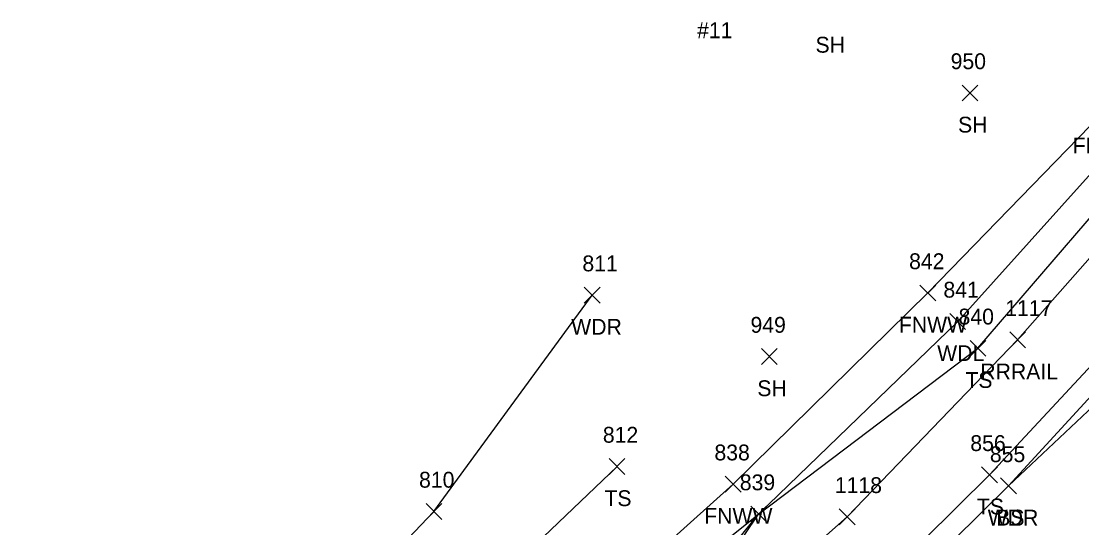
# Model space of a CAD drawing. Extents: x 1764889 to 1767296, y 695936 to 698960.
# Drawn here: x 1766131.8 to 1766265.6, y 696453.4 to 696517.3 of the extents above; entities that cross this region are included whole.
import ezdxf

# ---------------------------------------------------------------- set-up
doc = ezdxf.new("R2010")
doc.units = 0
for name, color, linetype in [('L_A', 7, 'Continuous'), ('L_I', 7, 'Continuous'), ('L_TIC', 7, 'Continuous'), ('LAWA', 7, 'Continuous'), ('LELB', 7, 'Continuous'), ('LFNC', 7, 'Continuous'), ('R_A', 7, 'Continuous'), ('R_I', 7, 'Continuous'), ('R_TIC', 7, 'Continuous'), ('RR', 7, 'Continuous'), ('U_C', 7, 'Continuous')]:
    doc.layers.add(name, color=color, linetype=linetype)

msp = doc.modelspace()

# ---------------------------------------------------------------- linework, layer by layer
at = {"layer": 'L_TIC'}
for points in [[(1766250.52, 696507.28), (1766252.52, 696509.28)], [(1766252.52, 696507.28), (1766250.52, 696509.28)], [(1766202.84, 696481.78), (1766204.84, 696483.78)], [(1766204.84, 696481.78), (1766202.84, 696483.78)], [(1766245.19, 696482.05), (1766247.19, 696484.05)], [(1766247.19, 696482.05), (1766245.19, 696484.05)], [(1766248.96, 696478.46), (1766250.96, 696480.46)], [(1766250.96, 696478.46), (1766248.96, 696480.46)], [(1766251.52, 696475.07), (1766253.52, 696477.07)], [(1766253.52, 696475.07), (1766251.52, 696477.07)], [(1766225.19, 696474.03), (1766227.19, 696476.03)], [(1766227.19, 696474.03), (1766225.19, 696476.03)], [(1766205.98, 696460.16), (1766207.98, 696462.16)], [(1766207.98, 696460.16), (1766205.98, 696462.16)], [(1766252.97, 696459.11), (1766254.97, 696461.11)], [(1766254.97, 696459.11), (1766252.97, 696461.11)], [(1766220.63, 696457.93), (1766222.63, 696459.93)], [(1766222.63, 696457.93), (1766220.63, 696459.93)], [(1766255.38, 696457.71), (1766257.38, 696459.71)], [(1766257.38, 696457.71), (1766255.38, 696459.71)], [(1766255.38, 696457.71), (1766257.38, 696459.71)], [(1766257.38, 696457.71), (1766255.38, 696459.71)], [(1766182.88, 696454.49), (1766184.88, 696456.49)], [(1766184.88, 696454.49), (1766182.88, 696456.49)], [(1766223.84, 696454.16), (1766225.84, 696456.16)], [(1766225.84, 696454.16), (1766223.84, 696456.16)], [(1766223.84, 696454.16), (1766225.84, 696456.16)], [(1766225.84, 696454.16), (1766223.84, 696456.16)], [(1766223.84, 696454.16), (1766225.84, 696456.16)], [(1766225.84, 696454.16), (1766223.84, 696456.16)]]:
    msp.add_lwpolyline(points, dxfattribs=at)
at = {"layer": 'LAWA'}
for points in [[(1766155.54, 696397.9), (1766161.77, 696405.44), (1766181.88, 696420.14), (1766196.06, 696430.7), (1766216.12, 696448.15), (1766224.84, 696455.16), (1766249.96, 696479.46), (1766272.12, 696504.03), (1766288.24, 696524.91), (1766311.88, 696556.72), (1766301.19, 696567.63)], [(1766161.11, 696377.48), (1766185.12, 696394.62), (1766212.55, 696417.35), (1766235.34, 696437.94), (1766256.38, 696458.71), (1766279.26, 696480.23), (1766298.66, 696503.53), (1766311.89, 696514.91), (1766320.79, 696513.88), (1766319.44, 696504.93), (1766321.82, 696491.21)], [(1766142.08, 696412.96), (1766162.91, 696433.47), (1766183.88, 696455.49), (1766203.84, 696482.78)]]:
    msp.add_lwpolyline(points, dxfattribs=at)
at = {"layer": 'LELB'}
for points in [[(1766158.91, 696379.33), (1766183.1, 696397.73), (1766210.95, 696420.2), (1766233.27, 696439.62), (1766253.97, 696460.11), (1766276.48, 696484.28), (1766294.63, 696506.78), (1766322.62, 696540.3)], [(1766256.38, 696458.71), (1766277.79, 696482.01), (1766297.06, 696504.51), (1766322.62, 696540.3)], [(1766150.56, 696387.79), (1766167.12, 696399.48), (1766186.95, 696417.34), (1766197.67, 696430.72), (1766217.09, 696445.57), (1766224.84, 696455.16), (1766252.52, 696476.07), (1766275.69, 696502.98), (1766288.24, 696524.91)], [(1766150.99, 696407.72), (1766172.83, 696427.73), (1766192.16, 696447.01), (1766206.98, 696461.16)], [(1766200.91, 696429.4), (1766217.78, 696444.64), (1766224.84, 696455.16)]]:
    msp.add_lwpolyline(points, dxfattribs=at)
at = {"layer": 'LFNC'}
msp.add_lwpolyline([(1766153.45, 696402.19), (1766162.21, 696408.4), (1766181.16, 696422.27), (1766195.92, 696435.85), (1766221.63, 696458.93), (1766246.19, 696483.05), (1766268.13, 696505.66), (1766282.49, 696526.8), (1766295.32, 696553.41), (1766299.86, 696566.71)], dxfattribs=at)
at = {"layer": 'R_TIC'}
for points in [[(1766256.52, 696476.14), (1766258.52, 696478.14)], [(1766258.52, 696476.14), (1766256.52, 696478.14)], [(1766235.01, 696453.81), (1766237.01, 696455.81)], [(1766237.01, 696453.81), (1766235.01, 696455.81)]]:
    msp.add_lwpolyline(points, dxfattribs=at)
at = {"layer": 'RR'}
msp.add_lwpolyline([(1766299.86, 696528.94), (1766277.75, 696500.06), (1766257.52, 696477.14), (1766236.01, 696454.81), (1766202.65, 696425.22), (1766159.82, 696390.23), (1766109.4, 696350.61)], dxfattribs=at)

# ---------------------------------------------------------------- texts
at = {"layer": 'L_A'}
for s, p in [('SH', (1766232.02, 696513.36)), ('SH', (1766250.01, 696503.28)), ('FNWW', (1766264.47, 696500.66)), ('WDR', (1766201.2, 696477.78)), ('FNWW', (1766242.54, 696478.05)), ('WDL', (1766247.37, 696474.46)), ('TS', (1766250.93, 696471.07)), ('SH', (1766224.68, 696470.03)), ('TS', (1766205.39, 696456.16)), ('TS', (1766252.38, 696455.11)), ('FNWW', (1766217.98, 696453.93)), ('WDR', (1766253.75, 696453.71)), ('BS', (1766254.82, 696453.71))]:
    msp.add_text(s, height=2, dxfattribs=at).set_placement(p)
at = {"layer": 'L_I'}
for s, p in [('950', (1766249.07, 696511.28)), ('811', (1766202.61, 696485.78)), ('842', (1766243.83, 696486.05)), ('841', (1766248.16, 696482.46)), ('840', (1766250.07, 696479.07)), ('949', (1766223.82, 696478.03)), ('812', (1766205.19, 696464.16)), ('856', (1766251.55, 696463.11)), ('838', (1766219.27, 696461.93)), ('855', (1766254.02, 696461.71)), ('855', (1766254.02, 696461.71)), ('810', (1766182, 696458.49)), ('839', (1766222.47, 696458.16)), ('839', (1766222.47, 696458.16)), ('839', (1766222.47, 696458.16))]:
    msp.add_text(s, height=2, dxfattribs=at).set_placement(p)
at = {"layer": 'R_A'}
msp.add_text('RRRAIL', height=2, dxfattribs=at).set_placement((1766252.81, 696472.14))
at = {"layer": 'R_I'}
for s, p in [('1117', (1766255.96, 696480.14)), ('1118', (1766234.46, 696457.81))]:
    msp.add_text(s, height=2, dxfattribs=at).set_placement(p)
at = {"layer": 'U_C'}
msp.add_text('#11', height=2, dxfattribs=at).set_placement((1766217.08, 696515.19))

doc.saveas('drawing.dxf')
